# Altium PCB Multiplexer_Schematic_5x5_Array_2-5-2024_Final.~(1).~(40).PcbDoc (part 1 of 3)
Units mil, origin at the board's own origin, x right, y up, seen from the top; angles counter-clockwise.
Board outline 7305 x 4000 mil, 8 copper layers (Loop Shield 1, Loop Trace, Loop Shield 2, GND 1, DC Signal 1, DC Signal 2, GND 2 (RF), RF), stack 74.018 mil thick; 89 components, 122 nets, 436 pads, 3654 vias.
Unrouted connection lines stored in the file: 2.
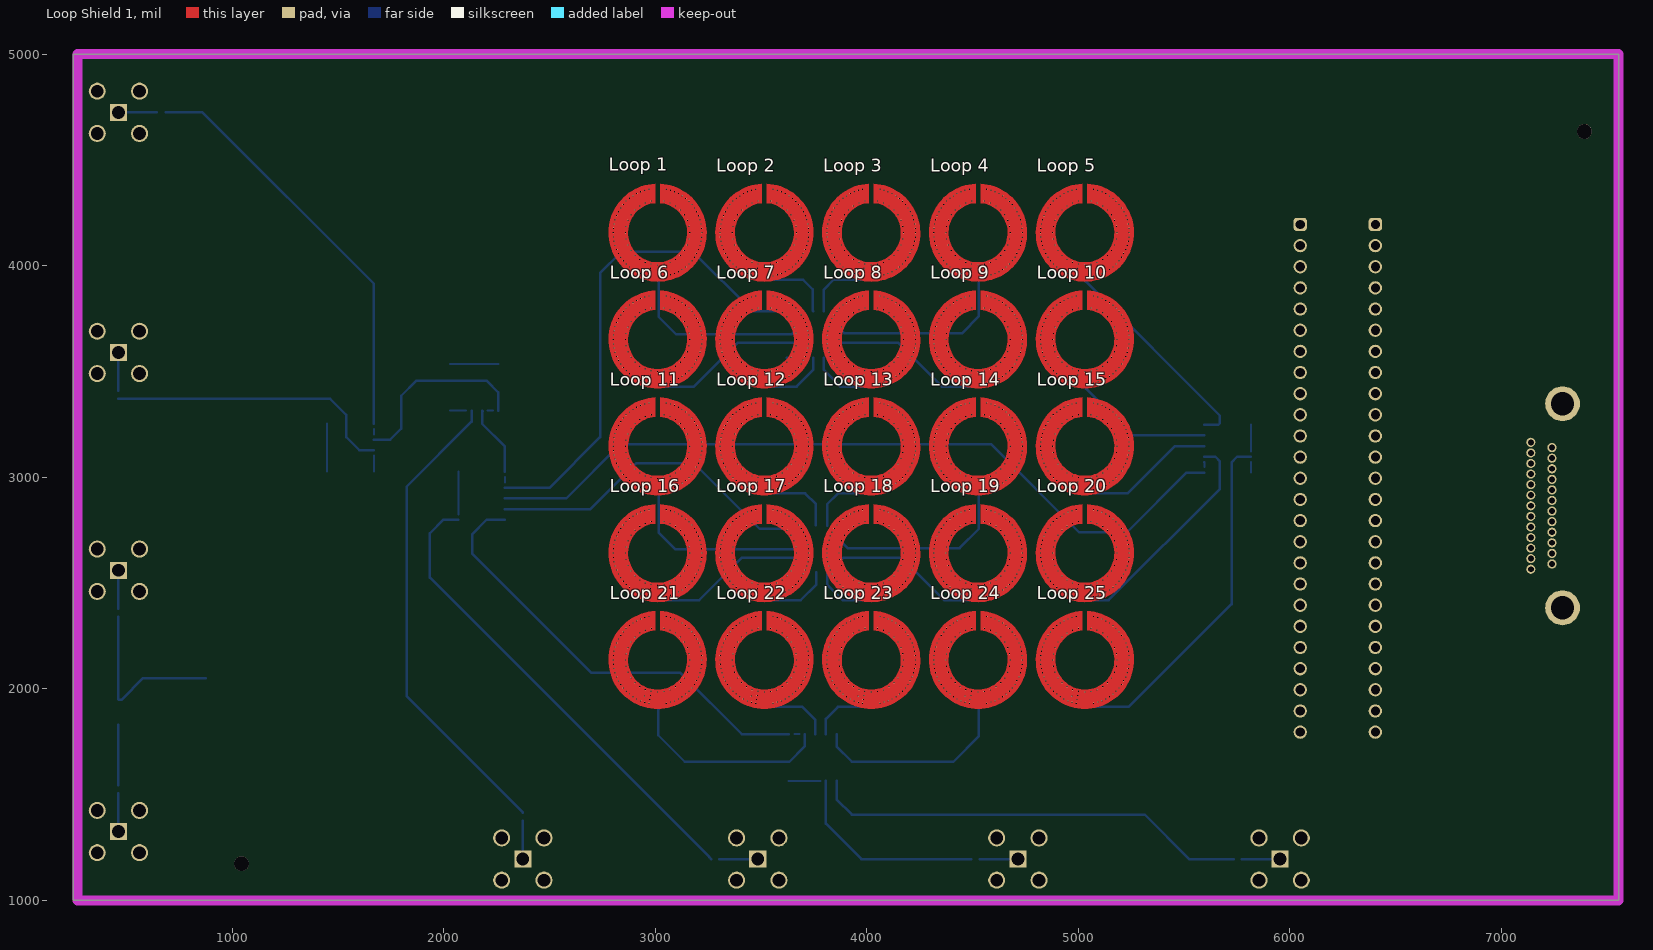
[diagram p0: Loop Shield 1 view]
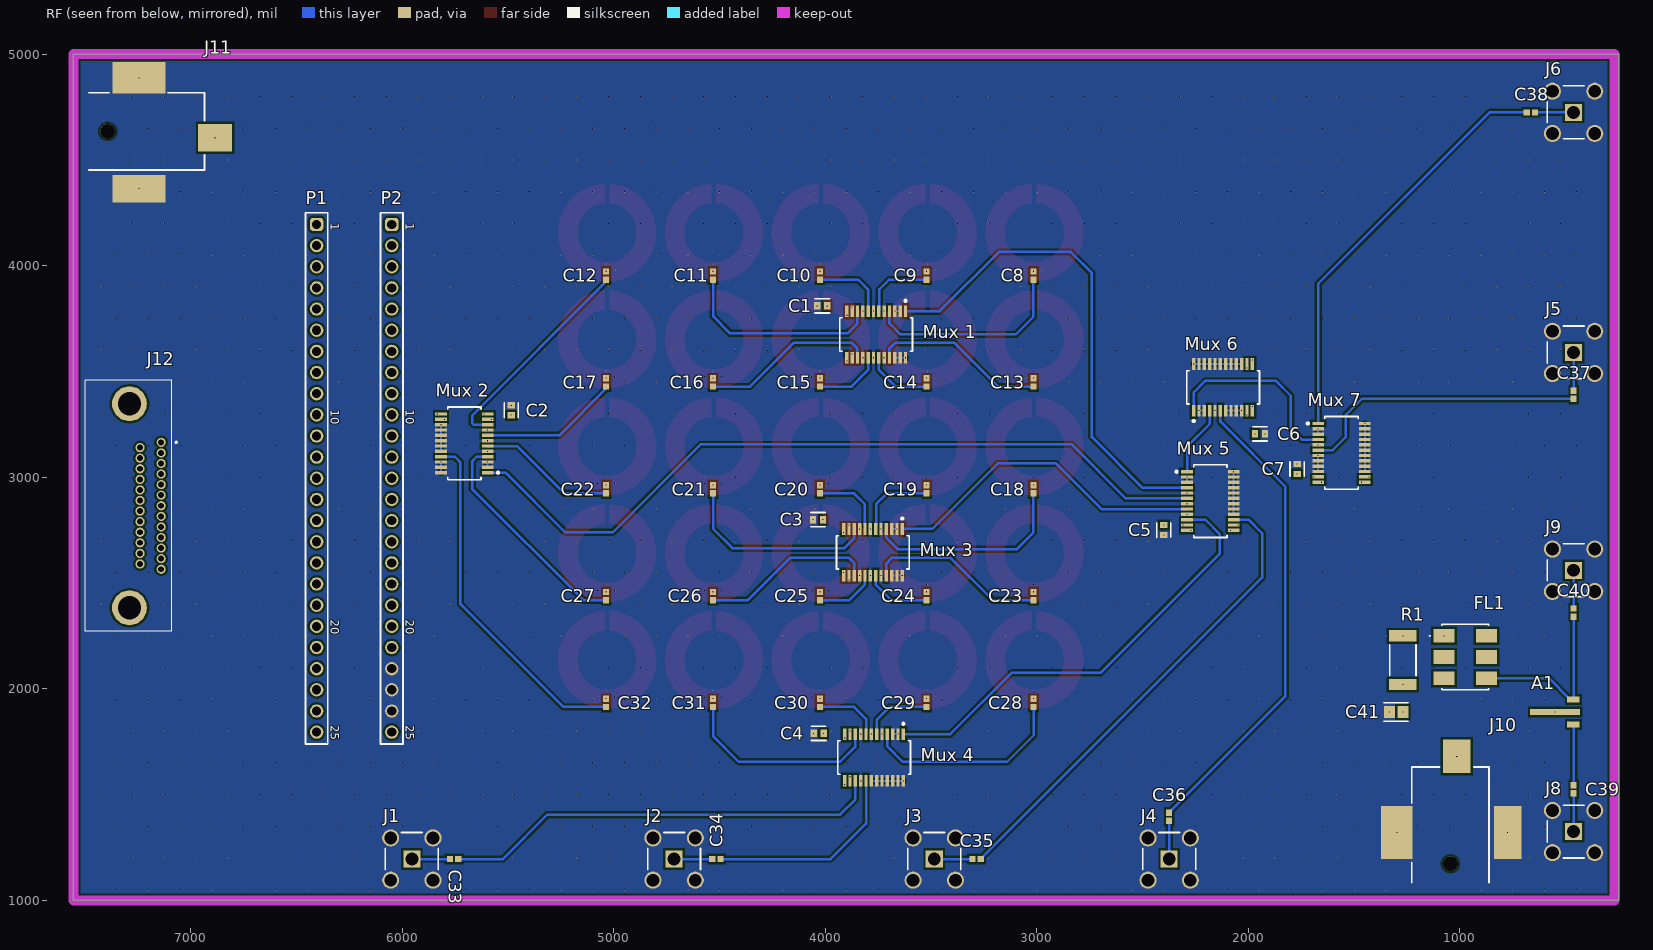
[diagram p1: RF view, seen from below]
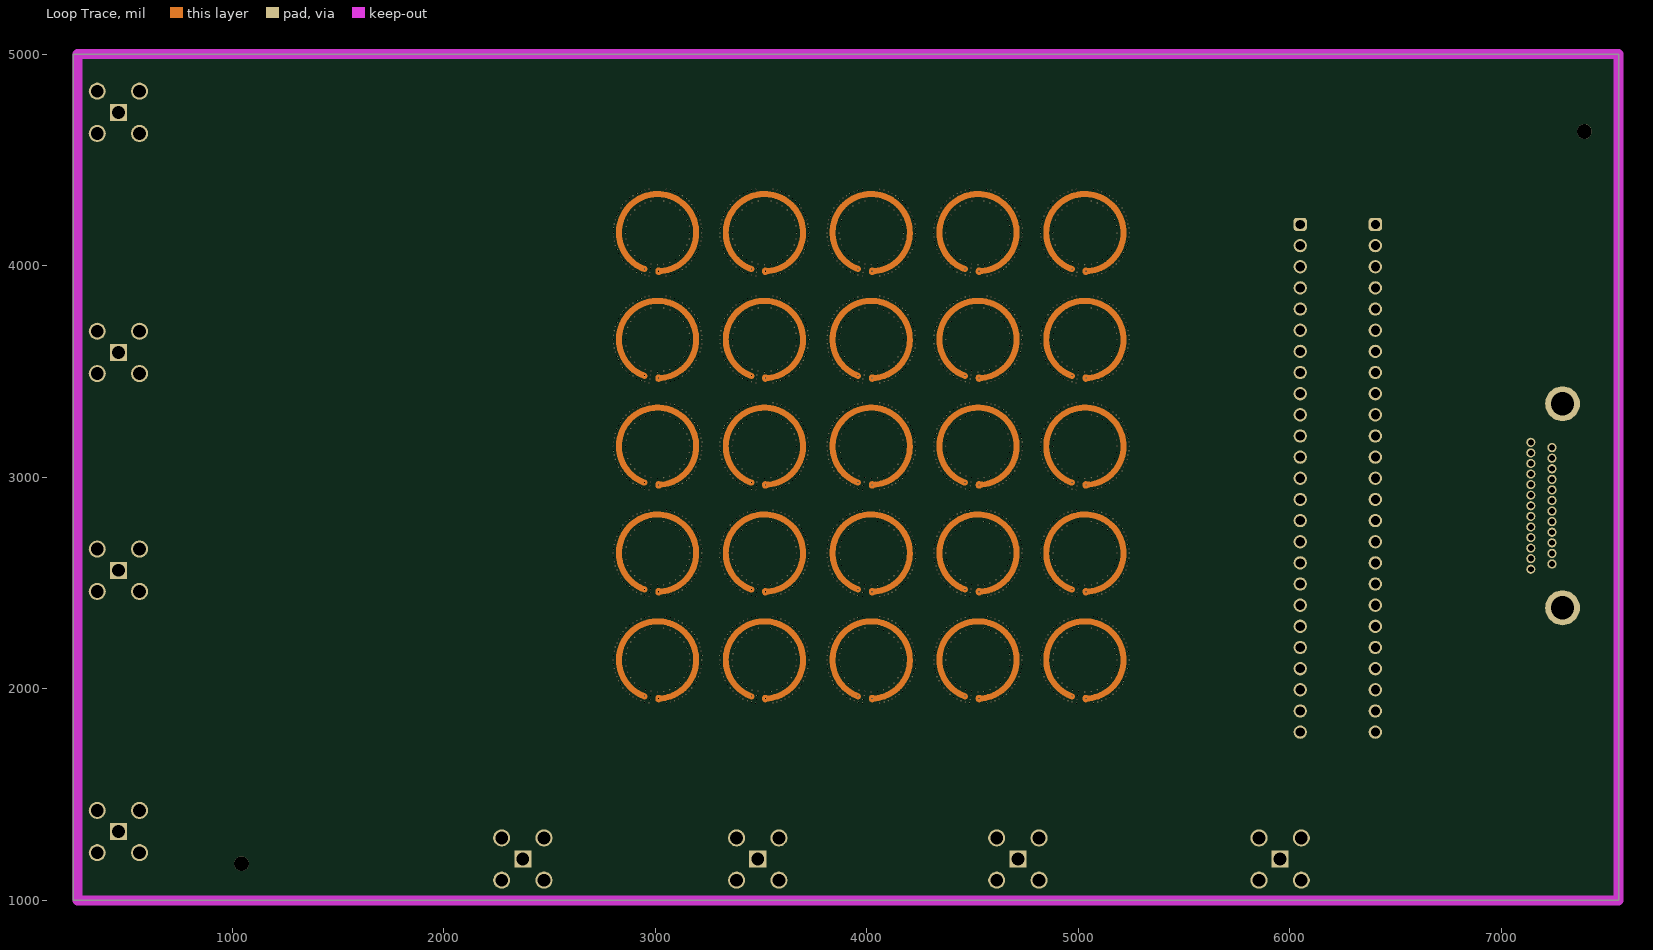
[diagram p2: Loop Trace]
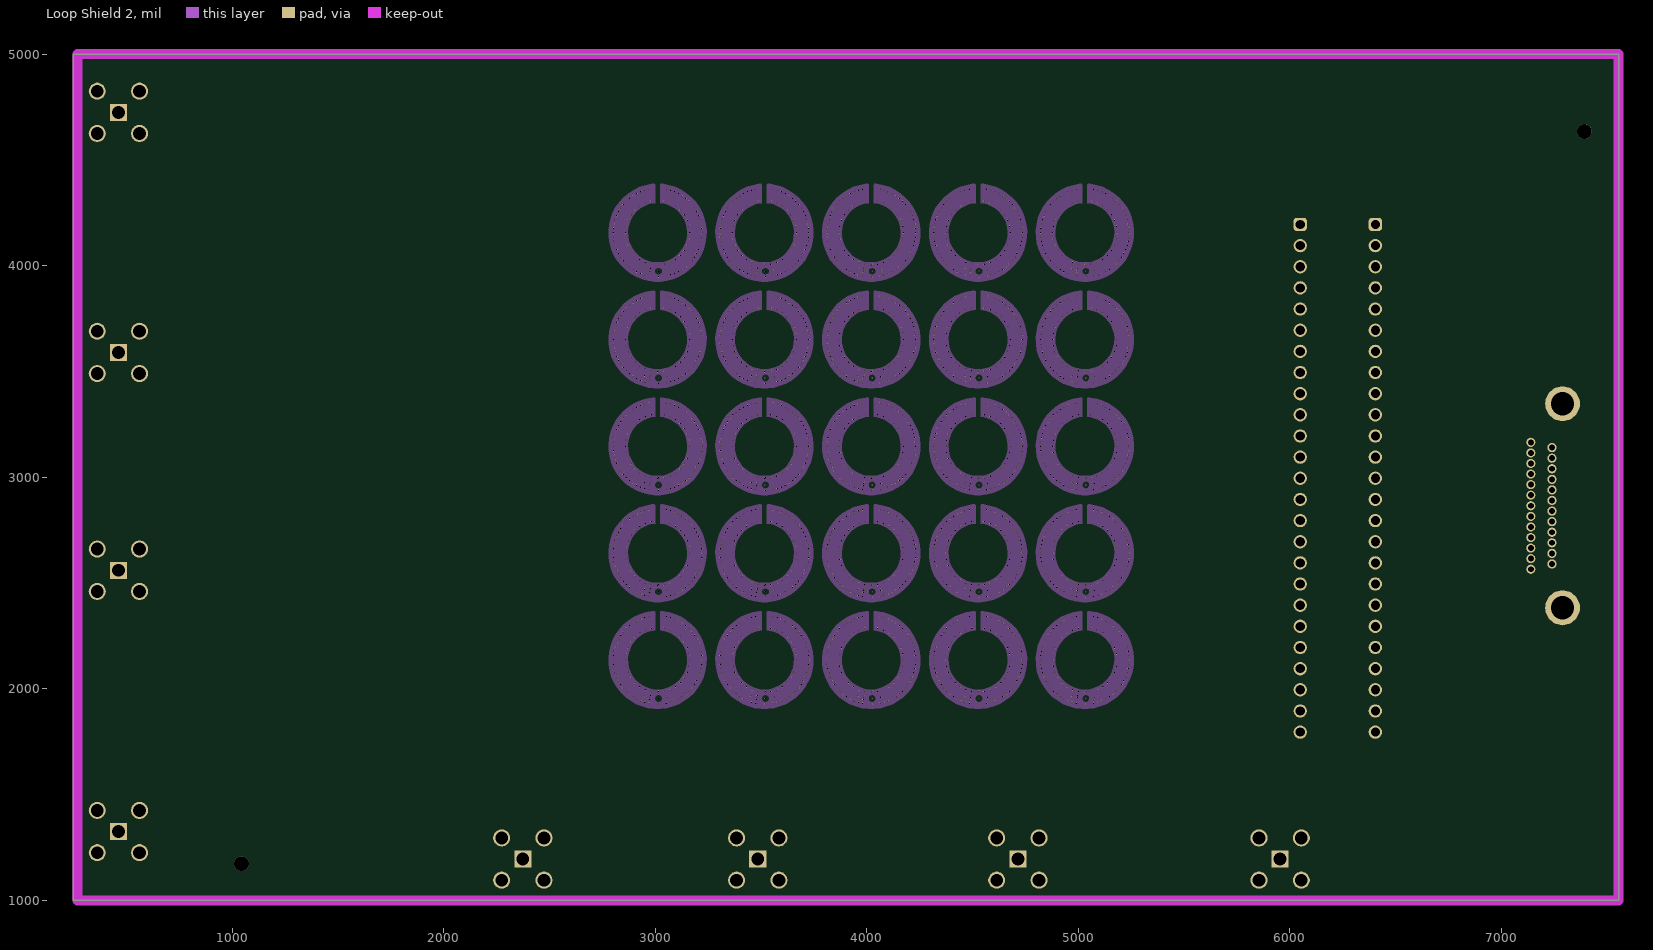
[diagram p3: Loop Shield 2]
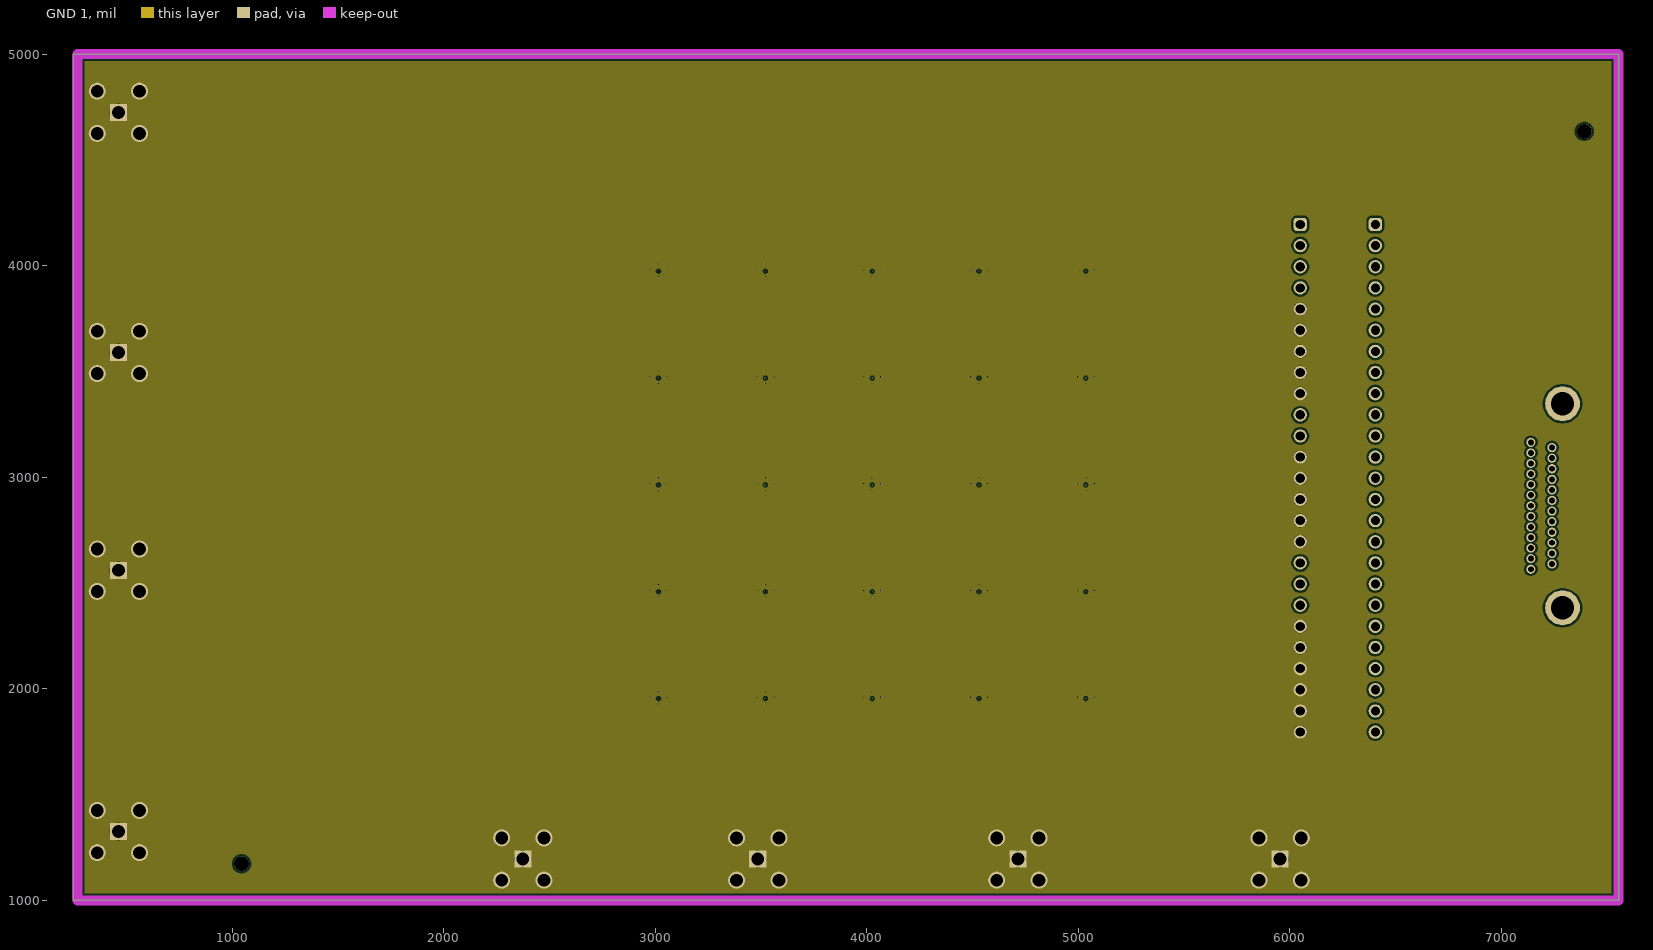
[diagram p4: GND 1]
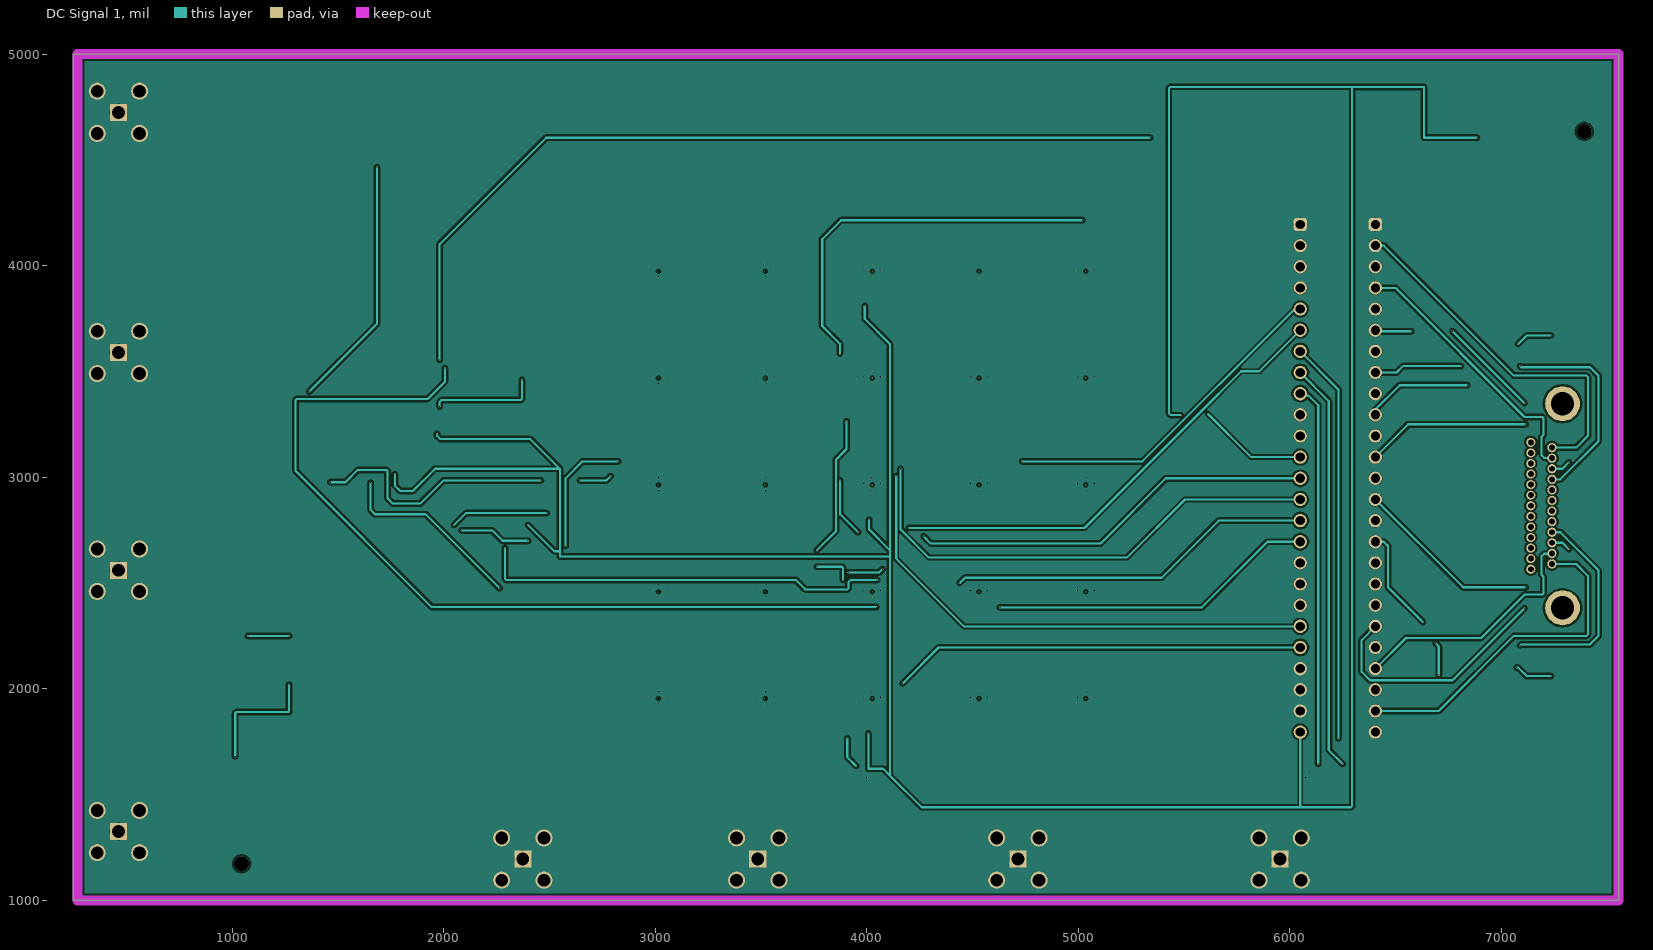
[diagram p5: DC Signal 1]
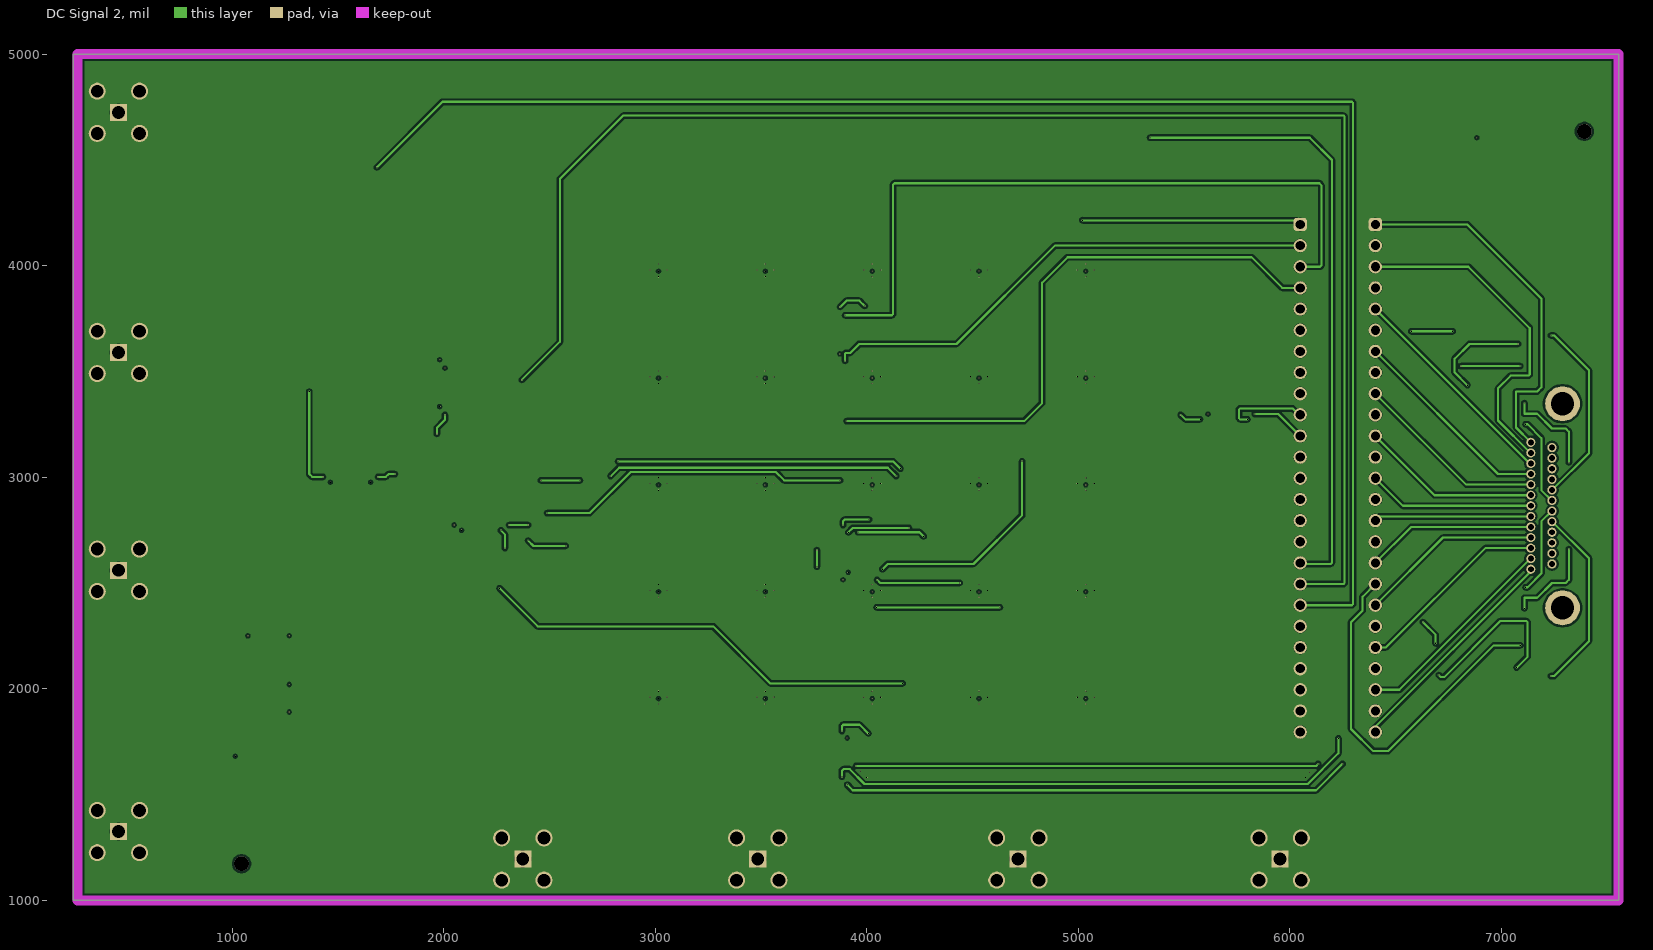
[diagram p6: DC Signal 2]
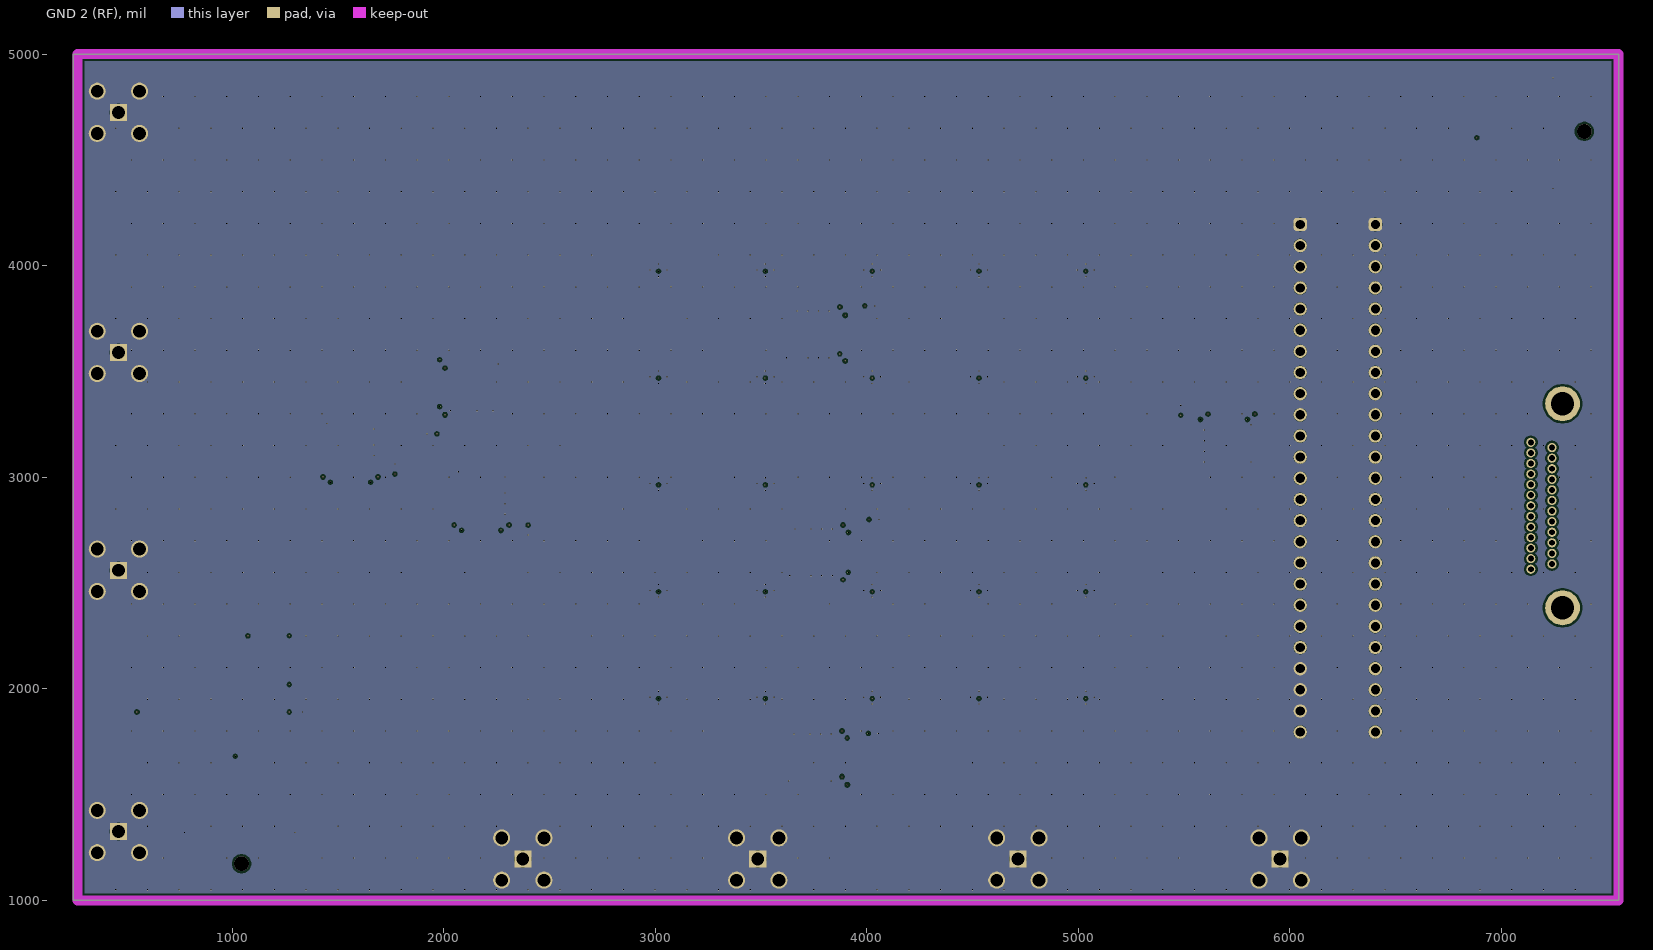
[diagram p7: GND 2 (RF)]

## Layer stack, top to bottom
Top Solder: solder mask 0.4, Solder Resist, Dk 3.5
Loop Shield 1: signal copper 2.756
Dielectric 1: prepreg 7.087, PP-006, Dk 4.2
Loop Trace: signal copper 2.756
Dielectric 2: core 7.874, FR-4, Dk 4.2
Loop Shield 2: signal copper 2.756
Dielectric 3: prepreg 7.087, FR-4, Dk 4.2
GND 1: signal copper 2.756
Dielectric 4: core 7.874, FR-4, Dk 4.2
DC Signal 1: signal copper 2.756
Dielectric 5: prepreg 7.087, FR-4, Dk 4.2
DC Signal 2: signal copper 2.756
Dielectric 6: core 7.874, FR-4, Dk 4.2
GND 2 (RF): signal copper 2.756
Dielectric 7: prepreg 7.087, PP-006, Dk 4.2
RF: signal copper 2.756
Bottom Solder: solder mask 0.4, Solder Resist, Dk 3.5

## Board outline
250,1000 7555,1000 7555,5000 250,5000

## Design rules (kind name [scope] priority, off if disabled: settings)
Clearance "Stitching GND" [IsStitchingVia and InNet('GND') vs (IsVia and (Not IsStitchingVia)) Or IsPad] p1: gap=5 ignorepadtopadclearanceinfootprint=FALSE
Clearance [All] p2: gap=10 ignorepadtopadclearanceinfootprint=FALSE except(0: Arc-SMDPad Arc-Via Arc-Hole Track-SMDPad Track-Via Track-Hole SMDPad-SMDPad SMDPad-Via SMDPad-Hole THPad-Hole Via-Hole Fill-Hole Poly-Hole Region-Hole Text-Hole)
HoleSize [All] p1: absolutevalues=TRUE maxlimit=130 minlimit=1 maxpercent=80.000 minpercent=20.000
HoleToHoleClearance [All] p1: gap=0 allowstackedmicrovias=TRUE
MinimumSolderMaskSliver MinimumSolderMaskSliver_1 [All] p1: minsoldermaskwidth=0
PlaneConnect [All] p1: planeconnectstyle=Direct reliefexpansion=20 reliefentries=4 reliefconductorwidth=10 reliefairgap=10
PolygonConnect [All] p1: connectstyle=Direct reliefconductorwidth=10 reliefentries=4 polygonreliefangle="90 Angle" airgapwidth=10
RoutingVias [All] p1: holewidth=10 width=12 viastyle="Through Hole" minholewidth=4 minwidth=6 maxholewidth=45 maxwidth=110
ShortCircuit [All] p1: allowed=TRUE
SolderMaskExpansion [All] p1: expansion=4 istentingtop=FALSE
ViasUnderSMD [All] p1: allowed=TRUE
Width RF [InNetClass('RF')] p1: maxlimit=56.26 minlimit=1 preferedwidth=24.42 toplayer_minwidth=11.81 toplayer_prefwidth=12.02 midlayer1_minwidth=11.81 midlayer1_maxwidth=24.42 midlayer1_prefwidth=11.81 midlayer2_minwidth=11.81 midlayer2_maxwidth=24.42 midlayer2_prefwidth=11.81 midlayer3_maxwidth=30 midlayer3_prefwidth=11.81 midlayer4_minwidth=11.81 midlayer4_maxwidth=24.42 midlayer4_prefwidth=11.81 midlayer5_minwidth=20 midlayer6_minwidth=20 bottomlayer_minwidth=11.81 bottomlayer_maxwidth=11.81 bottomlayer_prefwidth=11.81 minimp=50.000000 maximp=50.000000 favimp=50.000000 // RF Impedance
Width [InNet('VCC')] p2: maxlimit=56.26 minlimit=1 preferedwidth=10 toplayer_minwidth=56.26 toplayer_prefwidth=56.26 midlayer1_minwidth=24.42 midlayer1_maxwidth=24.42 midlayer1_prefwidth=24.42 midlayer2_minwidth=10 midlayer2_maxwidth=10 midlayer3_maxwidth=24.42 midlayer3_prefwidth=24.42 midlayer4_minwidth=24.42 midlayer4_maxwidth=24.42 midlayer4_prefwidth=24.42 midlayer5_minwidth=10 midlayer5_maxwidth=10 midlayer6_minwidth=10 midlayer6_maxwidth=10 bottomlayer_minwidth=10 bottomlayer_maxwidth=25 minimp=50.000000 maximp=50.000000 favimp=50.000000
25 further rules are at their usual default settings.

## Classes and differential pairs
net class RF: NetA1_1 NetA1_3 NetC8_1 NetC8_2 NetC9_1 NetC9_2 NetC10_1 NetC10_2 NetC11_1 NetC11_2 NetC12_1 NetC12_2 NetC13_1 NetC13_2 NetC14_1 NetC14_2 NetC15_1 NetC15_2 NetC16_1 NetC16_2 NetC17_1 NetC17_2 NetC18_1 NetC18_2 NetC19_1 NetC19_2 NetC20_1 NetC20_2 NetC21_1 NetC21_2 NetC22_1 NetC22_2 NetC23_1 NetC23_2 NetC24_1 NetC24_2 NetC25_1 NetC25_2 NetC26_1 NetC26_2 NetC27_1 NetC27_2 NetC28_1 NetC28_2 NetC29_1 NetC29_2 NetC30_1 NetC30_2 NetC31_1 NetC31_2 NetC32_2 NetC33_1 NetC33_2 NetC34_1 NetC34_2 NetC35_1 NetC35_2 NetC36_1 NetC36_2 NetC37_1 NetC37_2 NetC38_2 NetC39_1 NetC40_1 "Output Stage 1" "Output Stage 2" "Output Stage 3" "Output Stage 4" "Output Stage 5" "Output Stage 6" "Output Stage 7"

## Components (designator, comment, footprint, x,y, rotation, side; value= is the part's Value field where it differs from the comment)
A1 "GALI-52+" GALI-52+ 463.39,1890 r90 bottom
C1 "C0603C103J5RACTU" FP-C0603C-CF-MFG 4015,3810 r0 bottom value="10,000 pF"
C2 "C0603C103J5RACTU" FP-C0603C-CF-MFG 5485,3316.38 r90 bottom value="10,000 pF"
C3 "C0603C103J5RACTU" FP-C0603C-CF-MFG 4035,2800 r0 bottom value="10,000 pF"
C4 "C0603C103J5RACTU" FP-C0603C-CF-MFG 4031.88,1788.62 r0 bottom value="10,000 pF"
C5 "C0603C103J5RACTU" FP-C0603C-CF-MFG 2400,2750 r270 bottom value="10,000 pF"
C6 "C0603C103J5RACTU" FP-C0603C-CF-MFG 1945,3205 r180 bottom value="10,000 pF"
C7 "C0603C103J5RACTU" FP-C0603C-CF-MFG 1770,3038.62 r90 bottom value="10,000 pF"
C8 "GRM1555C1H101JA01D" CAPC1005X55X25ML05T10 3016.24,3953 r270 bottom
C9 "GRM1555C1H101JA01D" CAPC1005X55X25ML05T10 3521.24,3953 r270 bottom
C10 "GRM1555C1H101JA01D" CAPC1005X55X25ML05T10 4026.24,3953 r270 bottom
C11 "GRM1555C1H101JA01D" CAPC1005X55X25ML05T10 4531.24,3953 r270 bottom
C12 "GRM1555C1H101JA01D" CAPC1005X55X25ML05T10 5036.24,3953 r270 bottom
C13 "GRM1555C1H101JA01D" CAPC1005X55X25ML05T10 3016.24,3448 r270 bottom
C14 "GRM1555C1H101JA01D" CAPC1005X55X25ML05T10 3521.24,3448 r270 bottom
C15 "GRM1555C1H101JA01D" CAPC1005X55X25ML05T10 4026.24,3448 r270 bottom
C16 "GRM1555C1H101JA01D" CAPC1005X55X25ML05T10 4531.24,3448 r270 bottom
C17 "GRM1555C1H101JA01D" CAPC1005X55X25ML05T10 5036.24,3448 r270 bottom
C18 "GRM1555C1H101JA01D" CAPC1005X55X25ML05T10 3016.24,2943 r270 bottom
C19 "GRM1555C1H101JA01D" CAPC1005X55X25ML05T10 3521.24,2943 r270 bottom
C20 "GRM1555C1H101JA01D" CAPC1005X55X25ML05T10 4026.24,2943 r270 bottom
C21 "GRM1555C1H101JA01D" CAPC1005X55X25ML05T10 4531.24,2943 r270 bottom
C22 "GRM1555C1H101JA01D" CAPC1005X55X25ML05T10 5036.24,2943 r270 bottom
C23 "GRM1555C1H101JA01D" CAPC1005X55X25ML05T10 3016.24,2438 r270 bottom
C24 "GRM1555C1H101JA01D" CAPC1005X55X25ML05T10 3521.24,2438 r270 bottom
C25 "GRM1555C1H101JA01D" CAPC1005X55X25ML05T10 4026.24,2438 r270 bottom
C26 "GRM1555C1H101JA01D" CAPC1005X55X25ML05T10 4531.24,2438 r270 bottom
C27 "GRM1555C1H101JA01D" CAPC1005X55X25ML05T10 5036.24,2438 r270 bottom
C28 "GRM1555C1H101JA01D" CAPC1005X55X25ML05T10 3016.24,1933 r270 bottom
C29 "GRM1555C1H101JA01D" CAPC1005X55X25ML05T10 3521.24,1933 r270 bottom
C30 "GRM1555C1H101JA01D" CAPC1005X55X25ML05T10 4026.24,1933 r270 bottom
C31 "GRM1555C1H101JA01D" CAPC1005X55X25ML05T10 4531.24,1933 r270 bottom
C32 "GRM1555C1H101JA01D" CAPC1005X55X25ML05T10 5036.24,1933 r270 bottom
C33 "GRM1555C1H101JA01D" CAPC1005X55X25ML05T10 5755,1195 r180 bottom
C34 "GRM1555C1H101JA01D" CAPC1005X55X25ML05T10 4515,1195 r180 bottom
C35 "GRM1555C1H101JA01D" CAPC1005X55X25ML05T10 3285,1195 r180 bottom
C36 "GRM1555C1H101JA01D" CAPC1005X55X25ML05T10 2374.67,1395 r90 bottom
C37 "GRM1555C1H101JA01D" CAPC1005X55X25ML05T10 462.6,3390 r270 bottom
C38 "GRM1555C1H101JA01D" CAPC1005X55X25ML05T10 664.29,4725 r0 bottom
C39 "GRM1555C1H101JA01D" CAPC1005X55X25ML05T10 462.6,1525 r90 bottom
C40 "GRM1555C1H101JA01D" CAPC1005X55X25ML05T10 462.6,2360 r270 bottom
C41 "08051C104K4T2A" FP-0805-L_2_01_0_2-W_1_25-IPC_B 1301.72,1890 r0 bottom
FL1 "ADCH-1220+" ADCH1220 975,2150 r270 bottom
J1 "731000114" MOLX-731000114_V 5955,1195 r90 bottom
J2 "731000114" MOLX-731000114_V 4715,1195 r90 bottom
J3 "731000114" MOLX-731000114_V 3485.32,1195 r90 bottom
J4 "731000114" MOLX-731000114_V 2374.67,1195 r90 bottom
J5 "731000114" MOLX-731000114_V 462.6,3590 r0 bottom
J6 "731000114" MOLX-731000114_V 462.6,4725 r0 bottom
J8 "731000114" MOLX-731000114_V 462.6,1325 r0 bottom
J9 "731000114" MOLX-731000114_V 462.6,2560 r0 bottom
J10 "RASM722PTR13X" FP-RASM722PTR13X-MFG 1045,1340 r180 bottom
J11 "RASM722PTR13X" FP-RASM722PTR13X-MFG 7225.55,4634.92 r270 bottom
J12 "83614-9014" 836149014 7140,3165 r90 bottom
"Loop 1" "12mm H-Field Probe" PCBComponent_1 3015.5,4155 r0 top
"Loop 2" "12mm H-Field Probe" PCBComponent_1 3520.5,4155 r0 top
"Loop 3" "12mm H-Field Probe" PCBComponent_1 4025.5,4155 r0 top
"Loop 4" "12mm H-Field Probe" PCBComponent_1 4530.5,4155 r0 top
"Loop 5" "12mm H-Field Probe" PCBComponent_1 5035.5,4155 r0 top
"Loop 6" "12mm H-Field Probe" PCBComponent_1 3015.5,3650 r0 top
"Loop 7" "12mm H-Field Probe" PCBComponent_1 3520.5,3650 r0 top
"Loop 8" "12mm H-Field Probe" PCBComponent_1 4025.5,3650 r0 top
"Loop 9" "12mm H-Field Probe" PCBComponent_1 4530.5,3650 r0 top
"Loop 10" "12mm H-Field Probe" PCBComponent_1 5035.5,3650 r0 top
"Loop 11" "12mm H-Field Probe" PCBComponent_1 3015.5,3145 r0 top
"Loop 12" "12mm H-Field Probe" PCBComponent_1 3520.5,3145 r0 top
"Loop 13" "12mm H-Field Probe" PCBComponent_1 4025.5,3145 r0 top
"Loop 14" "12mm H-Field Probe" PCBComponent_1 4530.5,3145 r0 top
"Loop 15" "12mm H-Field Probe" PCBComponent_1 5035.5,3145 r0 top
"Loop 16" "12mm H-Field Probe" PCBComponent_1 3015.5,2640 r0 top
"Loop 17" "12mm H-Field Probe" PCBComponent_1 3520.5,2640 r0 top
"Loop 18" "12mm H-Field Probe" PCBComponent_1 4025.5,2640 r0 top
"Loop 19" "12mm H-Field Probe" PCBComponent_1 4530.5,2640 r0 top
"Loop 20" "12mm H-Field Probe" PCBComponent_1 5035.5,2640 r0 top
"Loop 21" "12mm H-Field Probe" PCBComponent_1 3015.5,2135 r0 top
"Loop 22" "12mm H-Field Probe" PCBComponent_1 3520.5,2135 r0 top
"Loop 23" "12mm H-Field Probe" PCBComponent_1 4025.5,2135 r0 top
"Loop 24" "12mm H-Field Probe" PCBComponent_1 4530.5,2135 r0 top
"Loop 25" "12mm H-Field Probe" PCBComponent_1 5035.5,2135 r0 top
"Mux 1" "HMC253AQS24E" FP-QS24E-MFG 3760,3675 r270 bottom
"Mux 2" "HMC253AQS24E" FP-QS24E-MFG 5706.7,3160 r0 bottom
"Mux 3" "HMC253AQS24E" FP-QS24E-MFG 3775,2645 r270 bottom
"Mux 4" "HMC253AQS24E" FP-QS24E-MFG 3770,1675 r270 bottom
"Mux 5" "HMC253AQS24E" FP-QS24E-MFG 2180,2887.37 r180 bottom
"Mux 6" "HMC253AQS24E" FP-QS24E-MFG 2120,3425 r90 bottom
"Mux 7" "HMC253AQS24E" FP-QS24E-MFG 1560,3115 r180 bottom
P1 "61302511121" 61302511121 6405,2995 r270 bottom
P2 "61302511121" 61302511121 6050,2995 r270 bottom
R1 "CRCW2512150RJNEG" FP-CRCW2512-e3-IPC_B 1270,2135 r270 bottom

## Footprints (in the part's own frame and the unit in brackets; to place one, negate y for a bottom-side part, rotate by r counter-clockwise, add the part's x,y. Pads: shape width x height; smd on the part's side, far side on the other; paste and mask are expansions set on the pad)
836149014 [mm]
  round 1.1 hole 0.71: 1(-15.24,0) 2(-13.97,0) 3(-12.7,0) 4(-11.43,0) 5(-10.16,0) 6(-8.89,0) 7(-7.62,0) 8(-6.35,0) 9(-5.08,0) 10(-3.81,0) 11(-2.54,0) 12(-1.27,0) 13(0,0) 14(-14.605,2.54) 15(-13.335,2.54) 16(-12.065,2.54) 17(-10.795,2.54) 18(-9.525,2.54) 19(-8.255,2.54) 20(-6.985,2.54) 21(-5.715,2.54) 22(-4.445,2.54) 23(-3.175,2.54) 24(-1.905,2.54) 25(-0.635,2.54)
  round 4.185 hole 2.79: MH1(-19.875,3.81) MH2(4.635,3.81)
  silkscreen extent -22.67,-1.9 7.43,9.13, body extent -22.64,-1.07 7.39,13.92, height 7.75
61302511121 [mm] "Pin Header, pitch 2.54 mm, THT, Vertical, single row, 25p"
  rrect50% 1.6x1.6 hole 1.1: 1(-30.48,0)
  round 1.6 hole 1.1: 2(-27.94,0) 3(-25.4,0) 4(-22.86,0) 5(-20.32,0) 6(-17.78,0) 7(-15.24,0) 8(-12.7,0) 9(-10.16,0) 10(-7.62,0) 11(-5.08,0) 12(-2.54,0) 13(0,0) 14(2.54,0) 15(5.08,0) 16(7.62,0) 17(10.16,0) 18(12.7,0) 19(15.24,0) 20(17.78,0) 21(20.32,0) 22(22.86,0) 23(25.4,0) 24(27.94,0) 25(30.48,0)
  silkscreen extent -31.9,-1.34 31.9,1.34, body extent -31.75,-1.27 31.75,1.27, height 8.57
ADCH1220 [mm]
  rect 1.65x2.54 smd: 1(-2.54,-2.54) 2(0,-2.54) 3(2.54,-2.54) 4(2.54,2.54) 5(0,2.54) 6(-2.54,2.54)
  silkscreen extent -3.94,-4.3 3.94,2.8, body extent -3.94,-3.64 3.94,3.64, height 5.33
CAPC1005X55X25ML05T10 [mm] "Chip Capacitor, 2-Leads, Body 1.00x0.50mm, IPC Low Density"
  rect 0.76x0.72 smd: 1(-0.49,0) 2(0.49,0)
  body extent -0.53,-0.28 0.53,0.27, height 0.55
FP-0805-L_2_01_0_2-W_1_25-IPC_B [mil]
  rect 51.36x57.33 smd paste+0 mask+0: 1(-31.72,0) 2(31.72,0)
  silkscreen extent -57,-44 57,44, body extent -40,-25 40,25, height 55
FP-C0603C-CF-MFG [mm]
  rect 0.75x0.9 smd paste+0 mask+0: 1(-0.6,0) 2(0.6,0)
  silkscreen extent -0.87,-0.85 0.88,0.85, body extent -0.8,-0.4 0.8,0.4, height 0.87
FP-CRCW2512-e3-IPC_B [mil]
  rect 53.34x130.24 smd paste+0 mask+0: 1(-115.18,0) 2(115.18,0)
  silkscreen extent -74,-62 74,62, body extent -124,-62 124,62, height 28
FP-QS24E-MFG [mm]
  rect 1.4x0.4 smd paste+0 mask+0: 1(-2.8,3.52) 2(-2.8,2.88) 3(-2.8,2.24) 4(-2.8,1.6) 5(-2.8,0.96) 6(-2.8,0.32) 7(-2.8,-0.32) 8(-2.8,-0.96) 9(-2.8,-1.6) 10(-2.8,-2.24) 11(-2.8,-2.88) 12(-2.8,-3.52) 13(2.8,-3.52) 14(2.8,-2.88) 15(2.8,-2.24) 16(2.8,-1.6) 17(2.8,-0.96) 18(2.8,-0.32) 19(2.8,0.32) 20(2.8,0.96) 21(2.8,1.6) 22(2.8,2.24) 23(2.8,2.88) 24(2.8,3.52)
  silkscreen extent -4.17,-4.37 2,4.37, body extent -3,-4.33 3,4.33, height 1.76
FP-RASM722PTR13X-MFG [mm]
  rect 3.3x4.06 smd paste+0 mask+0: 1(0.76,8.65)
  rect 3.81x6.35 smd paste+0 mask+0: 2(-6.43,-0.49)
  rect 3.3x6.35 smd paste+0 mask+0: 3(6.86,-0.49)
  round 1.78 hole 1.78 unplated paste-1000 mask+0: ""(0,-4.25)
  silkscreen extent -4.63,-6.5 4.63,7.38, body extent -7.6,-7.25 7.6,9.65, height 11
GALI-52+ [mm]
  rect 0.71x6 smd: GND1(0,2.2)
  rect 0.71x1.5 smd: IN(-1.5,0) OUT(1.5,0)
MOLX-731000114_V [mm] "Connector, 5-Leads, Body 14.8x6.35mm, Pitch 2.54mm"
  rect 2.05x2.05 hole 1.54: 1(0,0)
  round 2.05 hole 1.54: 2(-2.54,2.54) 3(-2.54,-2.54) 4(2.54,-2.54) 5(2.54,2.54)
  silkscreen extent -1.26,-3.17 3.17,3.17, body extent -11.62,-3.17 3.18,3.18, height 9.57
PCBComponent_1 [mil]
  round 1 on Mid3: 1(0.74,-181.37) 2(-65.31,-170.74)
  Loop Shield 1 region: -15.44,232.28 -127.77,196.54 -207.91,110.1 -235.06,-4.61 -202.16,-117.81 -117.77,-200.1 -3.78,-230.13 110.21,-200.1 194.6,-117.81 227.5,-4.61 200.35,110.1 120.21,196.54 7.88,232.28 7.88,232.28 7.88,141.13 74.67,117.65 121.51,64.57 136.49,-4.62 115.81,-72.32 64.73,-121.32 -3.78,-139.17 -72.28,-121.32 -123.37,-72.32 -144.05,-4.62 -129.07,64.57 -82.23,117.65 -15.44,141.13 -15.44,141.13
  Loop Shield 2 pour cut-out: 15.74,-181.37 14.6,-175.63 11.35,-170.76 6.49,-167.51 0.74,-166.37 0.74,-166.37 -5,-167.51 -9.86,-170.76 -13.11,-175.63 -14.26,-181.37 -14.26,-181.37 -13.11,-187.11 -9.86,-191.97 -5,-195.22 0.74,-196.37 0.74,-196.37 8.15,-194.5 13.64,-189.17 15.72,-181.82
  Loop Trace circle w1: c-65.31,-170.74 r9.18
  Loop Trace circle w1: c0.74,-181.37 r14.26
  Loop Trace region: -74.49,-170.74 -73.79,-174.26 -71.8,-177.23 -68.82,-179.22 -65.31,-179.92 -65.31,-179.92 -61.8,-179.22 -58.82,-177.23 -56.83,-174.26 -56.13,-170.74 -56.13,-170.74 -56.83,-167.23 -58.82,-164.26 -61.8,-162.27 -65.31,-161.57 -65.31,-161.57 -68.82,-162.27 -71.8,-164.26 -73.79,-167.23 -74.49,-170.74
  Loop Trace region: -13.52,-181.37 -12.43,-186.82 -9.34,-191.45 -4.71,-194.54 0.74,-195.63 0.74,-195.63 6.2,-194.54 10.83,-191.45 13.92,-186.82 15,-181.37 15,-181.37 13.92,-175.91 10.83,-171.28 6.2,-168.19 0.74,-167.11 0.74,-167.11 -4.71,-168.19 -9.34,-171.28 -12.43,-175.91 -13.52,-181.37
  Loop Trace lines w1: -73.87,-167.44 cw(c-65.31,-170.74) -56.13,-170.74 ; -73.87,-167.44 cw(c-65.31,-170.74) -56.13,-170.74 ; -73.87,-167.44 ccw(c-65.31,-170.74) -56.13,-170.74 ; -73.87,-167.44 ccw(c-65.31,-170.74) -56.13,-170.74 ; -73.87,-167.44 ccw(c-65.31,-170.74) -56.13,-170.74 ; -73.87,-167.44 cw(c-65.31,-170.74) -56.13,-170.74 ; -73.87,-167.44 cw(c-65.31,-170.74) -56.13,-170.74 ; -73.87,-167.44 ccw(c-65.31,-170.74) -56.13,-170.74 ; -73.87,-167.44 ccw(c-65.31,-170.74) -56.13,-170.74 ; -73.87,-167.44 ccw(c-65.31,-170.74) -56.13,-170.74 ; -73.87,-167.44 ccw(c-65.31,-170.74) -56.13,-170.74 ; -73.87,-167.44 cw(c-65.31,-170.74) -56.13,-170.74 ; -73.87,-167.44 cw(c-65.31,-170.74) -56.13,-170.74 ; -73.87,-167.44 cw(c-65.31,-170.74) -56.13,-170.74 ; 15,-181.37 cw(c0.74,-181.37) 14.98,-180.46 ; 15,-181.37 cw(c0.74,-181.37) 14.98,-180.46 ; 15,-181.37 cw(c0.74,-181.37) 14.98,-180.46 ; 15,-181.37 ccw(c0.74,-181.37) 14.98,-180.46 ; 15,-181.37 ccw(c0.74,-181.37) 14.98,-180.46 ; 15,-181.37 ccw(c0.74,-181.37) 14.98,-180.46 ; 15,-181.37 ccw(c0.74,-181.37) 14.98,-180.46 ; 15,-181.37 ccw(c0.74,-181.37) 14.98,-180.46 ; 15,-181.37 ccw(c0.74,-181.37) 14.98,-180.46 ; 15,-181.37 ccw(c0.74,-181.37) 14.98,-180.46 ; 15,-181.37 cw(c0.74,-181.37) 14.98,-180.46 ; 15,-181.37 cw(c0.74,-181.37) 14.98,-180.46 ; 15,-181.37 cw(c0.74,-181.37) 14.98,-180.46 ; 15,-181.37 cw(c0.74,-181.37) 14.98,-180.46
  Loop Trace lines w27.98: -73.87,-167.44 ccw(c-3.78,1.22) -65.31,-170.74 ; -73.87,-167.44 ccw(c-3.78,1.22) -65.31,-170.74 ; -73.87,-167.44 ccw(c-3.78,1.22) -65.31,-170.74 ; -73.87,-167.44 cw(c-3.78,1.22) 14.98,-180.46 ; -73.87,-167.44 cw(c-3.78,1.22) 14.98,-180.46 ; -73.87,-167.44 cw(c-3.78,1.22) 14.98,-180.46 ; -73.87,-167.44 cw(c-3.78,1.22) 14.98,-180.46 ; -73.87,-167.44 cw(c-3.78,1.22) 14.98,-180.46 ; -73.87,-167.44 cw(c-3.78,1.22) 14.98,-180.46 ; -73.87,-167.44 cw(c-3.78,1.22) 14.98,-180.46 ; -73.87,-167.44 ccw(c-3.78,1.22) -65.31,-170.74 ; -73.87,-167.44 ccw(c-3.78,1.22) -65.31,-170.74 ; -73.87,-167.44 ccw(c-3.78,1.22) -65.31,-170.74 ; -73.87,-167.44 ccw(c-3.78,1.22) -65.31,-170.74 ; -65.31,-170.74 cw(c-3.78,1.22) 0.74,-181.37 ; 0.74,-181.37 ccw(c-3.78,1.22) 14.98,-180.46 ; 0.74,-181.37 ccw(c-3.78,1.22) 14.98,-180.46 ; 0.74,-181.37 ccw(c-3.78,1.22) 14.98,-180.46 ; 0.74,-181.37 ccw(c-3.78,1.22) 14.98,-180.46 ; 0.74,-181.37 ccw(c-3.78,1.22) 14.98,-180.46 ; 0.74,-181.37 ccw(c-3.78,1.22) 14.98,-180.46 ; 0.74,-181.37 ccw(c-3.78,1.22) 14.98,-180.46

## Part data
A1: "RF Amplifier SMT Low Noise Amplifier, DC - 2000 MHz, 50", Package=None
C1 C2 C3 C4 C5 C6 C7: library part CMP-2006-03817-3, "Capacitor; Ceramic; Cap; .010uF; Tol 5%; SMT; Vol-Rtg 50V; X7R; Tape and Reel", Capacitance="10,000 pF", Manufacturer=KEMET, Package=C0603C-CF, Temperature="-55°C to +125°C", Temperature Characteristic=X7R, Temperature Coefficient=30ppm/°C, Temperature Range High=+125°C, Temperature Range Low=-55°C, Tolerance=0.05, Voltage Rating="50 V"
C8 C9 C10 C11 C12 C13 C14 C15 C16 C17 C18 C19 C20 C21 C22 C23 C24 C25 C26 C27 C28 C29 C30 C31 C32 C33 C34 C35 C36 C37 C38 C39 C40: library part CMP-2008-03915-1, Manufacturer=Murata
C41: library part CMP-2007-04172-2, "Automotive Ceramic Capacitor, 0805, 100nF, 10%, X7R, 15%, 100V", Capacitance=100nF, Case Code (Imperial)=0805, Case Code (Metric)=2012, Dielectric=X7R, Dielectric Material=Ceramic, Max Operating Temperature=125°C, Min Operating Temperature=-55°C, Package Quantity=1, Ratings=AEC-Q200, Tolerance=10%, Voltage=100V
FL1: "Filter", Manufacturer_Name=Mini-Circuits, Mouser Part Number=139-ADCH-1220+
J1 J2 J3 J4 J5 J6 J8 J9: library part CMP-2000-05487-1, "SMA Right-Angle PCB Jack Receptacle, Brass Body, Gold Plated, 50 Ohm, 5-Pin THD, RoHS, Tray", Manufacturer=Molex, Package Description="5-Pin Through Hole Device, Body 14.8 x 6.35 mm, Pitch 2.54 mm"
J10 J11: library part CMP-47995-000002-1, "CONN PWR JACK 2.1X5.5MM SOLDER", Case/Package=SMD/SMT, Color=Black, Current Rating=5A, Package Quantity=120
J12: "Connector", Manufacturer_Name=Molex, Mouser Part Number=538-83614-9014
"Mux 1" "Mux 2" "Mux 3" "Mux 4" "Mux 5" "Mux 6" "Mux 7": library part CMP-09141-000040-1, "IC RF SWITCH SP8T 2.5GHZ 24QSOP", Case/Package=SSOP, Max Operating Temperature=85°C, Min Operating Temperature=-40°C, Test Frequency=1GHz
P1 P2: library part CMP-1502-01112-2, Color=Black, Contact Resistance=20mΩ, Current Rating=3A, Operating Supply Voltage=250V
R1: library part CMP-02407-002320-1, "RES Thick Film, 150Ω, 5%, 1W, 200ppm/°C, 2512", Case Code (Imperial)=2512, Case Code (Metric)=6432, Max Operating Temperature=155°C, Max Power Dissipation=1W, Min Operating Temperature=-55°C, Package Quantity=2000, Resistance=150R, Temperature Coefficient=200ppm/°C, Tolerance=5%, Voltage Rating=500V

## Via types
v1: diameter 6, hole 4, Loop Shield 1 to Loop Shield 2, 2300 vias
v2: diameter 6, hole 4, GND 2 (RF) to RF, 1131 vias
v3: diameter 6, hole 4, Loop Shield 2 to RF, 75 vias
v4: diameter 6, hole 4, DC Signal 1 to DC Signal 2, 57 vias
v5: diameter 6, hole 4, DC Signal 1 to RF, 25 vias
v6: diameter 6, hole 4, Loop Shield 2 to GND 2 (RF), 25 vias
v7: diameter 6, hole 4, Loop Trace to RF, 25 vias
v8: diameter 6, hole 4, DC Signal 2 to RF, 16 vias

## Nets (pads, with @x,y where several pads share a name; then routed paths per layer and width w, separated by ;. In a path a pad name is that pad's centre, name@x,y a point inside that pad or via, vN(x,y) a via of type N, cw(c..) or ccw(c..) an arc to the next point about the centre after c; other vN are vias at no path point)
C0: "Mux 1.14" P2.1 | length 2880.5
  DC Signal 2 w10: v4(5020,4215) 5020.96,4214.04 6030.96,4214.04 P2.1@6050,4195
  DC Signal 1 w10: v5@3873.39,3585 3873.39,3631.61 3790,3715 3790,4125.76 3879.24,4215 v4(5020,4215)
  other v5: 3873.39,3583
C1: "Mux 1.13" P2.2 | length 2397.3
  DC Signal 2 w10: v8(3898.58,3550) 3898.58,3584.45 3901.46,3587.32 3922.32,3587.32 3965,3630 4425,3630 4890,4095 P2.2@6050,4095
C2: "Mux 1.12" P2.3 | length 3365.5
  DC Signal 2 w10: v8(3898.58,3765.55) 4119.52,3765.55 4125.37,3771.41 4125.37,4384.14 4131.23,4390 6140,4390 6150,4380 6150,4000.86 6144.14,3995 P2.3@6050,3995 P2.3@6042.37,4002.63
C3: "Mux 3.14" P2.4 | length 3787.9
  DC Signal 2 w10: v4(3765,2576.8) v4(3765,2655) ; v4(3905,3265) 4745,3265 4830,3350 4830,3920 4950,4040 5820,4040 5965,3895 P2.4@6050,3895
  DC Signal 1 w10: v4(3765,2576.8) 3882.53,2576.8 3888.39,2570.94 v5(3888.39,2515) ; v4(3765,2655) 3855,2745 3855,3083.42 3905,3133.42 v4(3905,3265)
C4: "Mux 3.13" P2.5 | length 2800.1
  DC Signal 2 w10: v4(4075,2565) 4100,2590 4505,2590 4735,2820 v4(4735,3075)
  DC Signal 1 w10: v5@3915,2550 4060,2550 v4(4075,2565) ; v4(4735,3075) 5303.48,3075 6023.48,3795 P2.5@6050,3795
  other v5: 3913.58,2550
C5: "Mux 3.12" P2.6 | length 2532.5
  DC Signal 2 w10: v8(3913.58,2739) 3934.58,2760 v4(4200,2760)
  DC Signal 1 w10: v4(4200,2760) 5029.8,2760 5564,3294.2 5564,3294.4 5770.53,3500.93 5855.93,3500.93 P2.6@6050,3695
C6: "Mux 4.14" P2.7 | length 4441.9
  DC Signal 2 w10: v8(3883.39,1584) 3883.39,1612.53 3890.86,1620 3920,1620 3990,1550 6085,1550 6230,1695 v4(6230,1765)
  DC Signal 1 w10: P2.7@6050,3595 6230,3415 v4(6230,1765)
C7: "Mux 4.13" P2.8 | length 4336.8
  DC Signal 2 w10: v8(3908.58,1546) 3934.58,1520 6125,1520 v4(6250,1645)
  DC Signal 1 w10: P2.8@6050,3495 6185,3360 6185,1710 v4(6250,1645)
C8: "Mux 4.12" P2.9 | length 4139.1
  DC Signal 2 w10: v4(3950,1635) 6125,1635 v4(6135,1645)
  DC Signal 1 w10: v5@3908.58,1765 3908.58,1676.42 v4(3950,1635) ; P2.9@6050,3395 6057.88,3387.12 6087.88,3387.12 6135,3340 v4(6135,1645)
  other v5: 3908.58,1767
C9: "Mux 2.14" P2.10 | length 387.2
  DC Signal 2 w10: v8(5800,3273.39) 5765.86,3273.39 5760,3279.24 5760,3319.14 5765.86,3325 6014.24,3325 6044.24,3295 P2.10@6050,3295
C10: "Mux 2.13" P2.11 | length 257.9
  DC Signal 2 w10: v8(5835,3298.58) 5946.42,3298.58 P2.11@6050,3195
C11: "Mux 2.12" P2.12 | length 520.3
  DC Signal 1 w10: v5(5614,3298.58) 5817.58,3095 P2.12@6050,3095
C12: "Mux 5.14" P2.13 | length 4461.4
  DC Signal 2 w10: v4(2490,2830) 2690,2830 2885,3025 3570,3025 3610,2985 v4(3875,2985) ; v4(3960,2740) 4250,2740 v4(4270,2720)
  DC Signal 1 w10: v5@2050,2775 2105.26,2830.26 2485.58,2830.26 ; v4(3875,2985) 3875,2825 v4(3960,2740) ; v4(4270,2720) 4304,2686 5105.8,2686 5414.8,2995 P2.13@6050,2995
  other v5: 2050,2773.99
C13: "Mux 5.13" P2.14 | length 4818.4
  DC Signal 2 w10: v4(2399.99,2700.01) 2425,2675 v4(2577.21,2675) ; v4(2825,3075) 4125,3075 v4(4160,3040)
  DC Signal 1 w10: v5(2085,2748.79) 2230.03,2748.79 2279.31,2699.51 v4@2399.48,2699.51 ; v4(2577.21,2675) 2577.21,2995.49 2656.72,3075 v4(2825,3075) ; v4(4160,3040) 4160,2754.39 4294.39,2620 5230,2620 5505,2895 P2.14@6050,2895
C14: "Mux 5.12" P2.15 | length 4181.7
  DC Signal 2 w10: v8(2271,2748.79) 2290,2729.79 v4(2290,2665) ; v4(4050,2515) 4065,2500 v4(4440,2500)
  DC Signal 1 w10: v4(2290,2665) 2290,2520.62 2295.86,2514.76 2296.09,2515 3665,2515 3710,2470 3909.14,2470 3915,2475.86 3915,2505 3925,2515 v4(4050,2515) v4@4049.76,2514.76 ; v4(4440,2500) 4465,2525 5394.8,2525 5664.8,2795 P2.15@6050,2795
C15: "Mux 6.14" P2.16 | length 6285.4
  DC Signal 2 w10: v4(4047,2385) v4(4630,2385)
  DC Signal 1 w10: v5(2006.61,3516) 2006.61,3451.61 1925,3370 1305.86,3370 1300,3364.14 1300,3030.2 1944.2,2386 v4@4046,2386 ; v4(4630,2385) 5585,2385 5895,2695 P2.16@6050,2695
C16: "Mux 6.13" P2.17 | length 7075.6
  DC Signal 2 w10: v4(5340,4605) 6095,4605 6200,4500 6200,2595.86 6194.14,2590 6055,2590 P2.17@6050,2595
  DC Signal 1 w10: v5(1981.42,3555) 1981.42,4101.22 2485.2,4605 v4(5340,4605)
C17: "Mux 6.12" P2.18 | length 7783.1
  DC Signal 2 w10: v4(2370,3460) 2550,3640 2550,4410 2850,4710 6254.14,4710 6260,4704.14 6260,2500.86 6254.14,2495 P2.18@6050,2495
  DC Signal 1 w10: v5(1981.42,3334) 1981.42,3356.42 1990,3365 2364.14,3365 2370,3370.86 v4(2370,3460)
C18: "Mux 7.14" P2.19 | length 9019.6
  DC Signal 2 w10: v4(1365,3405) 1365,3015 1378.39,3001.61 v8(1430,3001.61) ; v4(1685,4465) 1995,4775 6294.14,4775 6300,4769.14 6300,2400.86 6294.14,2395 P2.19@6050,2395
  DC Signal 1 w10: v4(1365,3405) 1685,3725 v4(1685,4465)
C19: "Mux 7.13" P2.20 | length 5360.7
  DC Signal 2 w10: v4(2460,2985) v4(2645,2985) ; v4(2790,3005) 2830,3045 4100,3045 v4(4140,3005)
  DC Signal 1 w10: v5(1465,2976.42) 1536.42,2976.42 1595,3035 1729.14,3035 1735,3029.14 1735,2900 1760,2875 1890,2875 2000,2985 v4(2460,2985) ; v4(2645,2985) 2770,2985 v4(2790,3005) ; v4(4140,3005) 4140,2615 4460,2295 P2.20@6050,2295
C20: "Mux 7.12" P2.21 | length 4934.6
  DC Signal 2 w10: v4(2265,2475) 2445,2295 3275,2295 3545,2025 v4(4170,2025)
  DC Signal 1 w10: v5@1655,2975 1655,2845.86 1675.86,2825 1915,2825 v4(2265,2475) ; v4(4170,2025) 4340,2195 P2.21@6050,2195
  other v5: 1655,2976.42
